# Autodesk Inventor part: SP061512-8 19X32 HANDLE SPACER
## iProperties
Company: MiniTec Framing Systems, LLC
Created: 2012-06
Part Number: SP061512-8 19X32 HANDLE SPACER
Material: Aluminum-6061
Description: PROFILE 19X32
Document SubType Name: Modeling
Designer: Administrator
Stock Number: 20.1000 PROFILE 19X32
Density: 2.71 g/cm^3
Mass: 53.0478 g
Surface Area: 91.1544 cm^2
Volume: 19.5748 cm^3
FINISH: CLEAR ANODIZED
Author: Administrator
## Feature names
1. Extrusion1
